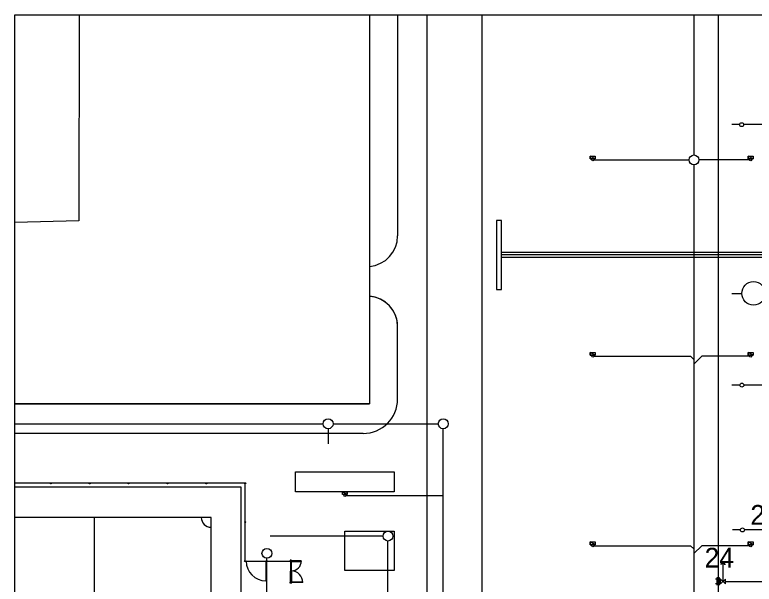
# Model space of a CAD drawing. Extents: x -263995 to -263575, y -1242437 to -1242140.
# Drawn here: x -263995.4 to -263920.5, y -1242197.8 to -1242140 of the extents above; entities that cross this region are included whole.
import ezdxf

# ---------------------------------------------------------------- set-up
doc = ezdxf.new("R2010")
doc.units = 0
for name, color, linetype in [('KFA_2D_SITUACIA_DSP', 7, 'Continuous'), ('KFA_BODY', 7, 'Continuous'), ('RAM_NA_TLAC_A3_1-1000', 7, 'Continuous')]:
    doc.layers.add(name, color=color, linetype=linetype)

msp = doc.modelspace()

# ---------------------------------------------------------------- linework, layer by layer
at = {"layer": 'KFA_2D_SITUACIA_DSP'}
for p, q in [((-263988.893, -1242140.046), (-263988.91, -1242160.93)), ((-263959.468, -1242140.046), (-263959.468, -1242179.482)), ((-263956.618, -1242140.046), (-263956.618, -1242162.449)), ((-263953.617, -1242244.458), (-263953.617, -1242140.046)), ((-263948.093, -1242140.046), (-263948.093, -1242241.458)), ((-263926.593, -1242140.046), (-263926.593, -1242154.252)), ((-263926.593, -1242140.046), (-263926.593, -1242154.252)), ((-263924.143, -1242140.046), (-263924.143, -1242185.14)), ((-263921.957, -1242151.182), (-263922.757, -1242151.182)), ((-263917.093, -1242151.182), (-263921.557, -1242151.182)), ((-263937.093, -1242154.652), (-263937.093, -1242154.362)), ((-263937.093, -1242154.362), (-263936.593, -1242154.362)), ((-263936.593, -1242154.652), (-263937.093, -1242154.362)), ((-263936.593, -1242154.652), (-263937.093, -1242154.362)), ((-263937.093, -1242154.362), (-263937.093, -1242154.652)), ((-263936.593, -1242154.362), (-263936.593, -1242154.652)), ((-263921.093, -1242154.652), (-263921.093, -1242154.362)), ((-263921.093, -1242154.362), (-263920.593, -1242154.362)), ((-263920.593, -1242154.652), (-263921.093, -1242154.362)), ((-263920.593, -1242154.652), (-263921.093, -1242154.362)), ((-263921.093, -1242154.362), (-263921.093, -1242154.652)), ((-263920.593, -1242154.362), (-263920.593, -1242154.652)), ((-263936.593, -1242154.652), (-263937.093, -1242154.652)), ((-263937.093, -1242154.652), (-263936.593, -1242154.652)), ((-263936.743, -1242154.752), (-263927.093, -1242154.752)), ((-263920.944, -1242154.752), (-263926.093, -1242154.752)), ((-263920.593, -1242154.652), (-263921.093, -1242154.652)), ((-263921.093, -1242154.652), (-263920.593, -1242154.652)), ((-263926.593, -1242155.252), (-263926.593, -1242204.252)), ((-263988.91, -1242160.93), (-263995.414, -1242161.113)), ((-263946.093, -1242160.882), (-263946.593, -1242160.882)), ((-263946.593, -1242160.882), (-263946.593, -1242167.882)), ((-263946.093, -1242167.882), (-263946.093, -1242160.882)), ((-263918.489, -1242164.132), (-263946.093, -1242164.132)), ((-263918.593, -1242164.382), (-263946.093, -1242164.382)), ((-263918.696, -1242164.632), (-263946.093, -1242164.632)), ((-263959.468, -1242165.549), (-263959.468, -1242165.549)), ((-263946.593, -1242167.882), (-263946.093, -1242167.882)), ((-263959.273, -1242168.601), (-263959.468, -1242168.582)), ((-263959.467, -1242168.582), (-263959.467, -1242168.582)), ((-263959.056, -1242168.638), (-263959.273, -1242168.601)), ((-263958.842, -1242168.69), (-263959.056, -1242168.638)), ((-263958.45, -1242168.829), (-263958.842, -1242168.69)), ((-263922.745, -1242168.282), (-263921.745, -1242168.282)), ((-263958.077, -1242169.024), (-263958.45, -1242168.829)), ((-263957.705, -1242169.291), (-263958.077, -1242169.024)), ((-263957.435, -1242169.549), (-263957.705, -1242169.291)), ((-263957.158, -1242169.893), (-263957.435, -1242169.549)), ((-263956.87, -1242170.411), (-263957.158, -1242169.893)), ((-263956.707, -1242170.894), (-263956.87, -1242170.411)), ((-263956.64, -1242171.257), (-263956.707, -1242170.894)), ((-263956.618, -1242171.626), (-263956.64, -1242171.257)), ((-263956.618, -1242178.982), (-263956.618, -1242171.626)), ((-263956.618, -1242178.982), (-263956.618, -1242171.645)), ((-263937.093, -1242174.553), (-263937.093, -1242174.263)), ((-263937.093, -1242174.263), (-263936.593, -1242174.263)), ((-263936.593, -1242174.553), (-263937.093, -1242174.263)), ((-263936.593, -1242174.553), (-263937.093, -1242174.263)), ((-263937.093, -1242174.263), (-263937.093, -1242174.553)), ((-263936.593, -1242174.553), (-263937.093, -1242174.553)), ((-263937.093, -1242174.553), (-263936.593, -1242174.553)), ((-263936.743, -1242174.653), (-263926.953, -1242174.653)), ((-263936.593, -1242174.263), (-263936.593, -1242174.553)), ((-263926.953, -1242174.653), (-263926.593, -1242174.978)), ((-263925.798, -1242174.653), (-263926.593, -1242175.448)), ((-263920.944, -1242174.653), (-263925.798, -1242174.653)), ((-263921.093, -1242174.553), (-263921.093, -1242174.263)), ((-263921.093, -1242174.263), (-263920.593, -1242174.263)), ((-263920.593, -1242174.553), (-263921.093, -1242174.263)), ((-263920.593, -1242174.553), (-263921.093, -1242174.263)), ((-263921.093, -1242174.263), (-263921.093, -1242174.553)), ((-263920.593, -1242174.553), (-263921.093, -1242174.553)), ((-263921.093, -1242174.553), (-263920.593, -1242174.553)), ((-263920.593, -1242174.263), (-263920.593, -1242174.553)), ((-263921.938, -1242177.582), (-263922.738, -1242177.582)), ((-263915.293, -1242177.582), (-263921.538, -1242177.582)), ((-263956.618, -1242178.982), (-263956.618, -1242178.982)), ((-263959.468, -1242179.482), (-263995.414, -1242179.482)), ((-263995.414, -1242179.482), (-263959.468, -1242179.482)), ((-263959.468, -1242179.482), (-263995.414, -1242179.482)), ((-263995.414, -1242181.5), (-263964.161, -1242181.5)), ((-263963.661, -1242182), (-263963.661, -1242183.528)), ((-263963.161, -1242181.5), (-263952.5, -1242181.5)), ((-263952, -1242222.527), (-263952, -1242182)), ((-263960.118, -1242182.482), (-263995.414, -1242182.482)), ((-263924.143, -1242185.14), (-263924.143, -1242250.14)), ((-263966.968, -1242186.382), (-263956.968, -1242186.382)), ((-263966.968, -1242188.382), (-263966.968, -1242186.382)), ((-263956.968, -1242186.382), (-263956.968, -1242188.382)), ((-263972.068, -1242187.532), (-263995.414, -1242187.532)), ((-263972.468, -1242187.932), (-263995.414, -1242187.932)), ((-263991.822, -1242187.532), (-263991.702, -1242187.532)), ((-263991.762, -1242187.592), (-263991.762, -1242187.472)), ((-263987.883, -1242187.532), (-263987.763, -1242187.532)), ((-263987.823, -1242187.592), (-263987.823, -1242187.472)), ((-263983.944, -1242187.532), (-263983.824, -1242187.532)), ((-263983.884, -1242187.592), (-263983.884, -1242187.472)), ((-263980.006, -1242187.532), (-263979.886, -1242187.532)), ((-263979.946, -1242187.592), (-263979.946, -1242187.472)), ((-263976.067, -1242187.532), (-263975.947, -1242187.532)), ((-263976.007, -1242187.592), (-263976.007, -1242187.472)), ((-263972.468, -1242294.032), (-263972.468, -1242187.932)), ((-263972.128, -1242187.532), (-263972.008, -1242187.532)), ((-263972.068, -1242187.592), (-263972.068, -1242187.472)), ((-263972.068, -1242195.407), (-263972.068, -1242187.532)), ((-263956.968, -1242188.382), (-263966.968, -1242188.382)), ((-263962.218, -1242188.382), (-263961.718, -1242188.382)), ((-263962.218, -1242188.672), (-263962.218, -1242188.382)), ((-263962.218, -1242188.382), (-263961.718, -1242188.672)), ((-263962.218, -1242188.382), (-263961.718, -1242188.672)), ((-263961.718, -1242188.382), (-263962.218, -1242188.382)), ((-263961.718, -1242188.672), (-263962.218, -1242188.672)), ((-263961.868, -1242188.772), (-263952, -1242188.772)), ((-263961.718, -1242188.382), (-263961.718, -1242188.672)), ((-263961.718, -1242188.672), (-263961.718, -1242188.382)), ((-263975.518, -1242190.982), (-263995.414, -1242190.982)), ((-263987.358, -1242190.982), (-263987.358, -1242207.482)), ((-263975.518, -1242290.982), (-263975.518, -1242190.982)), ((-263972.128, -1242191.47), (-263972.008, -1242191.47)), ((-263972.068, -1242191.41), (-263972.068, -1242191.53)), ((-263961.968, -1242192.382), (-263956.968, -1242192.382)), ((-263961.968, -1242196.382), (-263961.968, -1242192.382)), ((-263956.968, -1242192.382), (-263956.968, -1242196.382)), ((-263921.877, -1242192.257), (-263922.677, -1242192.257)), ((-263915.293, -1242192.257), (-263921.477, -1242192.257)), ((-263958.097, -1242192.883), (-263969.542, -1242192.883)), ((-263957.597, -1242243.932), (-263957.597, -1242193.383)), ((-263937.093, -1242193.752), (-263937.093, -1242193.462)), ((-263937.093, -1242193.462), (-263936.593, -1242193.462)), ((-263936.593, -1242193.752), (-263937.093, -1242193.462)), ((-263936.593, -1242193.752), (-263937.093, -1242193.462)), ((-263937.093, -1242193.462), (-263937.093, -1242193.752)), ((-263936.593, -1242193.752), (-263937.093, -1242193.752)), ((-263937.093, -1242193.752), (-263936.593, -1242193.752)), ((-263936.743, -1242193.852), (-263926.953, -1242193.852)), ((-263936.593, -1242193.462), (-263936.593, -1242193.752)), ((-263926.953, -1242193.852), (-263926.593, -1242194.178)), ((-263925.798, -1242193.852), (-263926.593, -1242194.648)), ((-263920.944, -1242193.852), (-263925.798, -1242193.852)), ((-263921.093, -1242193.752), (-263921.093, -1242193.462)), ((-263921.093, -1242193.462), (-263920.593, -1242193.462)), ((-263920.593, -1242193.752), (-263921.093, -1242193.462)), ((-263920.593, -1242193.752), (-263921.093, -1242193.462)), ((-263921.093, -1242193.462), (-263921.093, -1242193.752)), ((-263920.593, -1242193.752), (-263921.093, -1242193.752)), ((-263921.093, -1242193.752), (-263920.593, -1242193.752)), ((-263920.593, -1242193.462), (-263920.593, -1242193.752)), ((-263972.068, -1242195.407), (-263967.418, -1242195.407)), ((-263969.968, -1242195.407), (-263969.968, -1242197.407)), ((-263969.921, -1242210.683), (-263969.869, -1242195.133)), ((-263967.413, -1242195.307), (-263967.513, -1242195.307)), ((-263967.513, -1242195.307), (-263967.513, -1242195.407)), ((-263967.513, -1242195.407), (-263967.413, -1242195.407)), ((-263967.425, -1242195.32), (-263967.5, -1242195.32)), ((-263967.5, -1242195.32), (-263967.5, -1242195.395)), ((-263967.5, -1242195.395), (-263967.425, -1242195.395)), ((-263967.463, -1242195.407), (-263967.463, -1242196.395)), ((-263967.388, -1242195.407), (-263967.463, -1242195.407)), ((-263967.425, -1242195.395), (-263967.425, -1242195.32)), ((-263967.425, -1242195.395), (-263967.425, -1242195.345)), ((-263967.425, -1242195.345), (-263967.325, -1242195.345)), ((-263967.413, -1242195.407), (-263967.413, -1242195.307)), ((-263967.413, -1242195.357), (-263967.363, -1242195.357)), ((-263967.388, -1242196.395), (-263967.388, -1242195.407)), ((-263967.363, -1242195.457), (-263967.388, -1242195.457)), ((-263966.388, -1242195.371), (-263967.375, -1242195.37)), ((-263967.375, -1242195.37), (-263967.375, -1242195.445)), ((-263967.375, -1242195.445), (-263966.388, -1242195.446)), ((-263967.363, -1242195.357), (-263967.363, -1242195.457)), ((-263967.325, -1242195.345), (-263967.325, -1242195.37)), ((-263923.768, -1242195.732), (-263923.768, -1242195.482)), ((-263923.768, -1242195.482), (-263923.518, -1242195.482)), ((-263923.643, -1242197.482), (-263923.643, -1242195.607)), ((-263923.518, -1242195.482), (-263923.518, -1242195.732)), ((-263967.463, -1242197.557), (-263967.463, -1242196.42)), ((-263967.388, -1242196.42), (-263967.388, -1242197.557)), ((-263956.968, -1242196.382), (-263961.968, -1242196.382)), ((-263923.768, -1242195.732), (-263923.893, -1242195.732)), ((-263923.518, -1242195.732), (-263923.393, -1242195.732)), ((-263924.018, -1242197.107), (-263924.268, -1242197.107)), ((-263924.268, -1242197.107), (-263924.268, -1242197.857)), ((-263924.018, -1242197.857), (-263924.018, -1242197.107)), ((-263967.513, -1242197.557), (-263967.413, -1242197.557)), ((-263967.513, -1242197.657), (-263967.513, -1242197.557)), ((-263967.413, -1242197.657), (-263967.513, -1242197.657)), ((-263967.5, -1242197.57), (-263967.425, -1242197.57)), ((-263967.5, -1242197.645), (-263967.5, -1242197.57)), ((-263967.425, -1242197.645), (-263967.5, -1242197.645)), ((-263967.388, -1242197.557), (-263967.463, -1242197.557)), ((-263967.425, -1242197.57), (-263967.425, -1242197.62)), ((-263967.425, -1242197.57), (-263967.425, -1242197.645)), ((-263967.425, -1242197.62), (-263967.325, -1242197.62)), ((-263967.413, -1242197.557), (-263967.413, -1242197.657)), ((-263967.413, -1242197.607), (-263967.363, -1242197.607)), ((-263967.363, -1242197.507), (-263967.388, -1242197.507)), ((-263967.375, -1242197.52), (-263966.238, -1242197.52)), ((-263967.375, -1242197.595), (-263967.375, -1242197.52)), ((-263966.238, -1242197.595), (-263967.375, -1242197.595)), ((-263967.363, -1242197.607), (-263967.363, -1242197.507)), ((-263967.325, -1242197.62), (-263967.325, -1242197.595)), ((-263923.893, -1242197.232), (-263924.393, -1242197.232)), ((-263923.893, -1242197.732), (-263924.393, -1242197.732)), ((-263924.143, -1242197.482), (-263923.893, -1242197.482)), ((-263923.893, -1242197.482), (-263924.143, -1242197.482)), ((-263923.893, -1242197.732), (-263923.893, -1242197.232)), ((-263923.893, -1242197.232), (-263923.393, -1242197.732)), ((-263923.393, -1242197.232), (-263923.893, -1242197.732)), ((-263923.393, -1242197.732), (-263923.393, -1242197.232)), ((-263923.393, -1242197.482), (-263915.293, -1242197.482))]:
    msp.add_line(p, q, dxfattribs=at)
for centre, radius in [((-263921.757, -1242151.182), 0.2), ((-263926.593, -1242154.752), 0.5), ((-263936.843, -1242154.752), 0.1), ((-263920.844, -1242154.752), 0.1), ((-263920.55, -1242168.282), 1.195), ((-263936.843, -1242174.653), 0.1), ((-263920.844, -1242174.653), 0.1), ((-263921.738, -1242177.582), 0.2), ((-263963.661, -1242181.5), 0.5), ((-263952, -1242181.5), 0.5), ((-263991.762, -1242187.532), 0.06), ((-263987.823, -1242187.532), 0.06), ((-263983.884, -1242187.532), 0.06), ((-263979.946, -1242187.532), 0.06), ((-263976.007, -1242187.532), 0.06), ((-263972.068, -1242187.532), 0.06), ((-263961.968, -1242188.772), 0.1), ((-263972.068, -1242191.47), 0.06), ((-263957.597, -1242192.883), 0.5), ((-263921.677, -1242192.257), 0.2), ((-263969.868, -1242194.633), 0.5), ((-263936.843, -1242193.852), 0.1), ((-263920.844, -1242193.852), 0.1), ((-263972.068, -1242195.407), 0.06), ((-263969.868, -1242195.407), 0.06)]:
    msp.add_circle(centre, radius, dxfattribs=at)
for centre, radius, start, end in [((-263959.738, -1242162.441), 3.12, 274.96374, 359.8482), ((-263959.668, -1242171.626), 3.05, 359.64411, 86.21555), ((-263960.118, -1242178.982), 3.5, 270, 0), ((-263975.518, -1242190.982), 1, 180, 270), ((-263969.968, -1242195.407), 2, 180, 270), ((-263967.4, -1242195.382), 1.025, 270.60954, 0.60953), ((-263967.4, -1242197.582), 1.175, 359.39047, 89.39046)]:
    msp.add_arc(centre, radius, start, end, dxfattribs=at)
for centre in [(-263967.4, -1242195.382), (-263967.4, -1242195.382), (-263967.4, -1242197.582)]:
    msp.add_ellipse(centre, major_axis=(0, 0.0125), ratio=0.999995, dxfattribs=at)
at = {"layer": 'RAM_NA_TLAC_A3_1-1000'}
msp.add_lwpolyline([(-263995.414, -1242140.046), (-263575.414, -1242140.046), (-263575.414, -1242437.046), (-263995.414, -1242437.046)], close=True, dxfattribs=at)

# ---------------------------------------------------------------- texts
at = {"layer": 'KFA_BODY'}
for s, p in [('25', (-263920.874, -1242191.726)), ('24', (-263925.512, -1242196.069))]:
    msp.add_text(s, height=2, dxfattribs=at).set_placement(p)

doc.saveas('drawing.dxf')
